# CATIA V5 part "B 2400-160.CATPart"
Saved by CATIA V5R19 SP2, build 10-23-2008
Part number: B 2400-160
Bounding box of the stored display mesh (mm): x -37.351 to 37.351, y -37.351 to 37.351, z 0 to 430
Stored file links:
  C:\Users\Bora\Desktop\3D Katı model\B serisi\B 2400\B 2400-160.CATPart
  C:\Program Files\Dassault Systemes\B19\intel_a\reffiles\standard\MetricThickPitch.txt
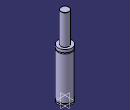
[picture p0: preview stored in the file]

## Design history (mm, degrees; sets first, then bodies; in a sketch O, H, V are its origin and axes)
Body1 (main body)
  Sketch1 on yz-plane, origin (0, 0, 0), H (0, 1, 0), V (0, 0, 1)
    point P3 (22.5, 429)
    point P5 (22.5, 429)
    point P10 (37.5, 246.5)
    point P11 (37.5, 251.5)
    point P13 (37.5, 251.5)
    point P14 (37.5, 246.5)
    line L1 (37.5, 0) -> (37.5, 8)
    line L2 (22.5, 429) -> (22.5, 267)
    arc A1 centre (21.5, 429) radius 1 from (22.5, 429) to (21.5, 430) ccw
    line L3 (33.5, 13) -> (33.5, 8)
    line L4 (37.5, 13) -> (37.5, 246.5)
    line L5 (37.5, 251.5) -> (37.5, 267)
    arc A2 centre (37.5, 249) radius 2.5 from (37.5, 251.5) to (37.5, 246.5) ccw
    line L6 (21.5, 430) -> (0, 430)
    point P15 (0, 430)
    line L7 (22.5, 267) -> (37.5, 267)
    line L8 (0, 0) -> (37.5, 0)
    line L9 (33.5, 8) -> (37.5, 8)
    line L10 (33.5, 13) -> (37.5, 13)
    coincidence: P15 V, P3 P5, P10 P14, P11 P13
    tangency: L6 A1
    horizontal: L7 H, L8 H, L9 H, L10 H
  Shaft1: profile Sketch1, axis Sketch1.V, angle 360
  Sketch2 on face of Shaft1 from Sketch1.L8, origin (0, 0, 0), H (1, 0, 0), V (0, -1, 0)
    point P1 (20, 0)
    distance P1 V = 20
  Hole1: placed by Sketch2, at (20, 0, 0) direction (0, 0, 1), diameter 6.647, depth 13, threaded "M8", thread diameter 8, thread depth 13, pitch 1.25
  CircPattern1: of Hole1, instances 4, angular step 90, axis from xy-plane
